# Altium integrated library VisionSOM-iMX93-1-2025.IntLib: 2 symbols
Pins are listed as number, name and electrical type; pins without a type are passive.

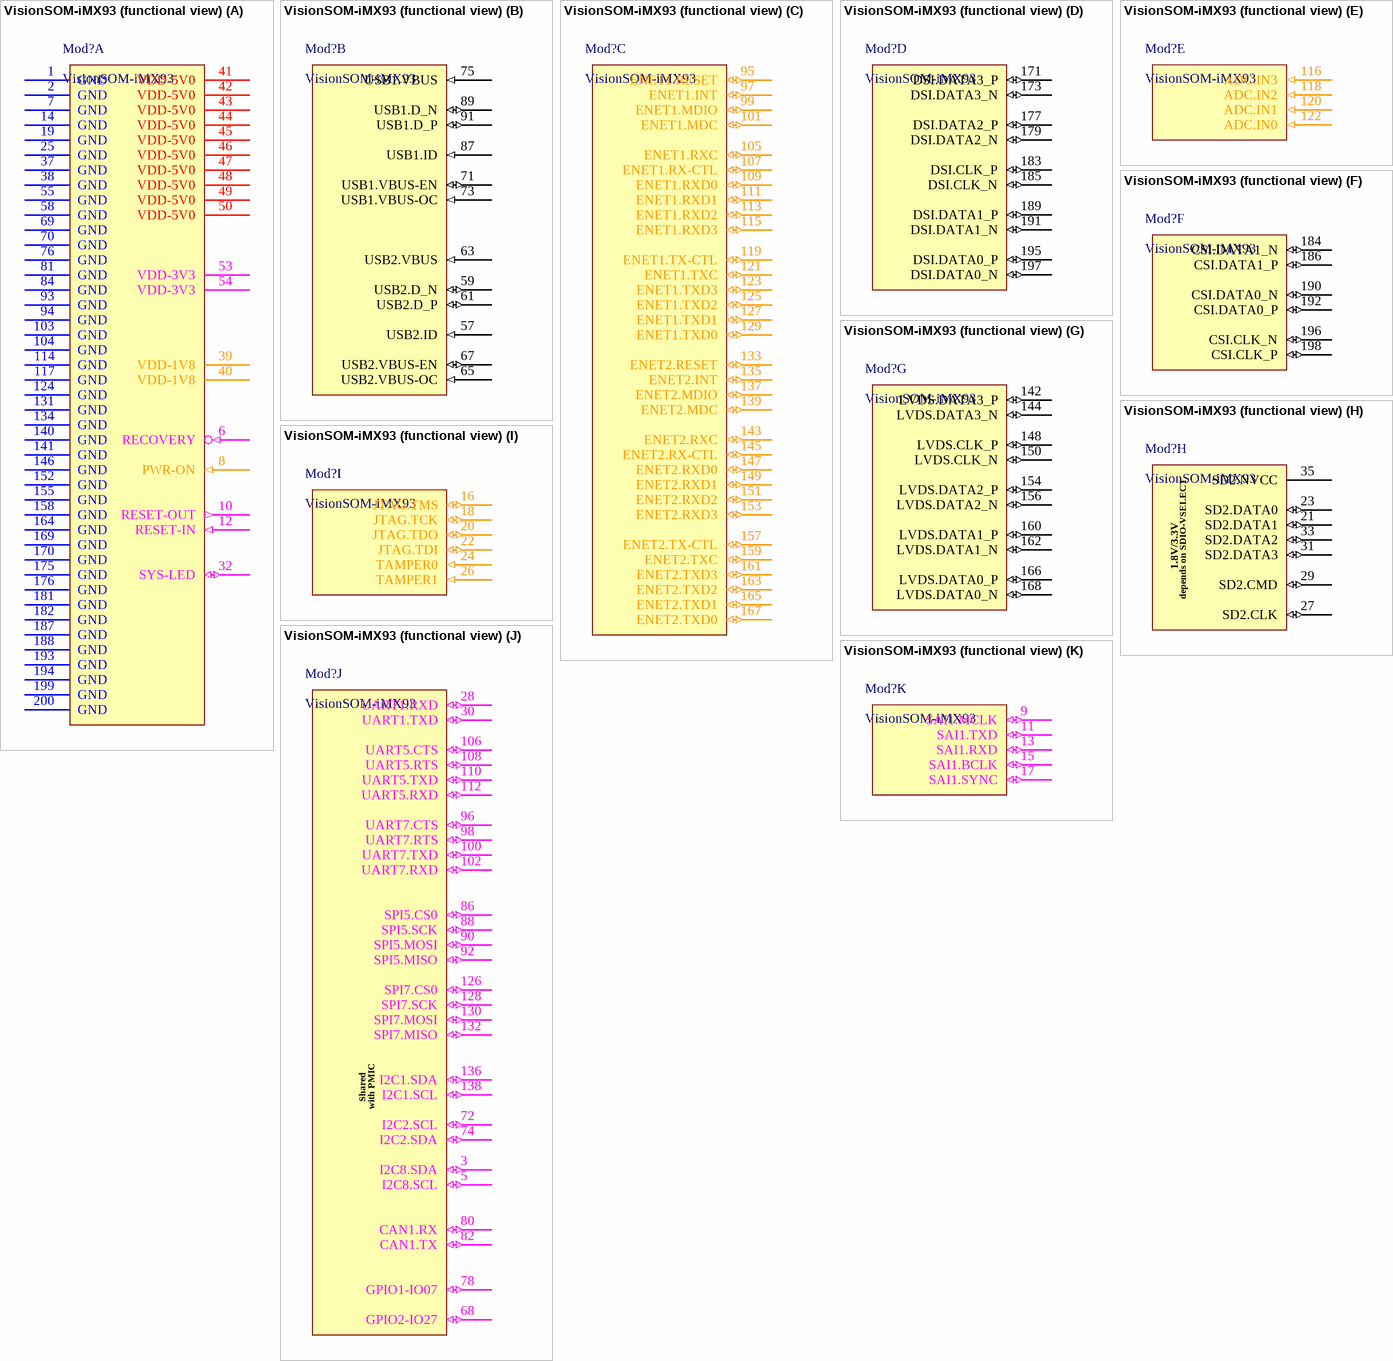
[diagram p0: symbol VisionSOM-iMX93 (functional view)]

## VisionSOM-iMX93 (functional view)
designator Mod?, comment VisionSOM-iMX93
VisionSOM-iMX93 (SLS26 module series)
footprint SODIMM200_1473005-4 (Classic SODIMM200 footprint with SOM mounting hole. / TE 1473005-4)
part A pins: 1 GND (power), 2 GND (power), 6 RECOVERY (in), 7 GND (power), 8 PWR-ON (in), 10 RESET-OUT (out), 12 RESET-IN (in), 14 GND (power), 19 GND (power), 25 GND (power), 32 SYS-LED (io), 37 GND (power), 38 GND (power), 39 VDD-1V8 (power), 40 VDD-1V8 (power), 41 VDD-5V0 (power), 42 VDD-5V0 (power), 43 VDD-5V0 (power), 44 VDD-5V0 (power), 45 VDD-5V0 (power), 46 VDD-5V0 (power), 47 VDD-5V0 (power), 48 VDD-5V0 (power), 49 VDD-5V0 (power), 50 VDD-5V0 (power), 53 VDD-3V3 (power), 54 VDD-3V3 (power), 55 GND (power), 58 GND (power), 69 GND (power), 70 GND (power), 76 GND (power), 81 GND (power), 84 GND (power), 93 GND (power), 94 GND (power), 103 GND (power), 104 GND (power), 114 GND (power), 117 GND (power), 124 GND (power), 131 GND (power), 134 GND (power), 140 GND (power), 141 GND (power), 146 GND (power), 152 GND (power), 155 GND (power), 158 GND (power), 164 GND (power), 169 GND (power), 170 GND (power), 175 GND (power), 176 GND (power), 181 GND (power), 182 GND (power), 187 GND (power), 188 GND (power), 193 GND (power), 194 GND (power), 199 GND (power), 200 GND (power)
part B pins: 57 USB2.ID (in), 59 USB2.D_N (io), 61 USB2.D_P (io), 63 USB2.VBUS (in), 65 USB2.VBUS-OC (in), 67 USB2.VBUS-EN (io), 71 USB1.VBUS-EN (io), 73 USB1.VBUS-OC (in), 75 USB1.VBUS (in), 87 USB1.ID (in), 89 USB1.D_N (io), 91 USB1.D_P (io)
part C pins: 95 ENET1.RESET (io), 97 ENET1.INT (io), 99 ENET1.MDIO (io), 101 ENET1.MDC (io), 105 ENET1.RXC (io), 107 ENET1.RX-CTL (io), 109 ENET1.RXD0 (io), 111 ENET1.RXD1 (io), 113 ENET1.RXD2 (io), 115 ENET1.RXD3 (io), 119 ENET1.TX-CTL (io), 121 ENET1.TXC (io), 123 ENET1.TXD3 (io), 125 ENET1.TXD2 (io), 127 ENET1.TXD1 (io), 129 ENET1.TXD0 (io), 133 ENET2.RESET (io), 135 ENET2.INT (io), 137 ENET2.MDIO (io), 139 ENET2.MDC (io), 143 ENET2.RXC (io), 145 ENET2.RX-CTL (io), 147 ENET2.RXD0 (io), 149 ENET2.RXD1 (io), 151 ENET2.RXD2 (io), 153 ENET2.RXD3 (io), 157 ENET2.TX-CTL (io), 159 ENET2.TXC (io), 161 ENET2.TXD3 (io), 163 ENET2.TXD2 (io), 165 ENET2.TXD1 (io), 167 ENET2.TXD0 (io)
part D pins: 171 DSI.DATA3_P (io), 173 DSI.DATA3_N (io), 177 DSI.DATA2_P (io), 179 DSI.DATA2_N (io), 183 DSI.CLK_P (io), 185 DSI.CLK_N (io), 189 DSI.DATA1_P (io), 191 DSI.DATA1_N (io), 195 DSI.DATA0_P (io), 197 DSI.DATA0_N (io)
part E pins: 116 ADC.IN3 (in), 118 ADC.IN2 (in), 120 ADC.IN1 (in), 122 ADC.IN0 (in)
part F pins: 184 CSI.DATA1_N (io), 186 CSI.DATA1_P (io), 190 CSI.DATA0_N (io), 192 CSI.DATA0_P (io), 196 CSI.CLK_N (io), 198 CSI.CLK_P (io)
part G pins: 142 LVDS.DATA3_P (io), 144 LVDS.DATA3_N (io), 148 LVDS.CLK_P (io), 150 LVDS.CLK_N (io), 154 LVDS.DATA2_P (io), 156 LVDS.DATA2_N (io), 160 LVDS.DATA1_P (io), 162 LVDS.DATA1_N (io), 166 LVDS.DATA0_P (io), 168 LVDS.DATA0_N (io)
part H pins: 21 SD2.DATA1 (io), 23 SD2.DATA0 (io), 27 SD2.CLK (io), 29 SD2.CMD (io), 31 SD2.DATA3 (io), 33 SD2.DATA2 (io), 35 SD2.NVCC (power)
part I pins: 16 JTAG.TMS (io), 18 JTAG.TCK (io), 20 JTAG.TDO (io), 22 JTAG.TDI (io), 24 TAMPER0 (in), 26 TAMPER1 (in)
part J pins: 3 I2C8.SDA (io), 5 I2C8.SCL (io), 28 UART1.RXD (io), 30 UART1.TXD (io), 68 GPIO2-IO27 (io), 72 I2C2.SCL (io), 74 I2C2.SDA (io), 78 GPIO1-IO07 (io), 80 CAN1.RX (io), 82 CAN1.TX (io), 86 SPI5.CS0 (io), 88 SPI5.SCK (io), 90 SPI5.MOSI (io), 92 SPI5.MISO (io), 96 UART7.CTS (io), 98 UART7.RTS (io), 100 UART7.TXD (io), 102 UART7.RXD (io), 106 UART5.CTS (io), 108 UART5.RTS (io), 110 UART5.TXD (io), 112 UART5.RXD (io), 126 SPI7.CS0 (io), 128 SPI7.SCK (io), 130 SPI7.MOSI (io), 132 SPI7.MISO (io), 136 I2C1.SDA (io), 138 I2C1.SCL (io)
part K pins: 9 SAI1.MCLK (io), 11 SAI1.TXD (io), 13 SAI1.RXD (io), 15 SAI1.BCLK (io), 17 SAI1.SYNC (io)

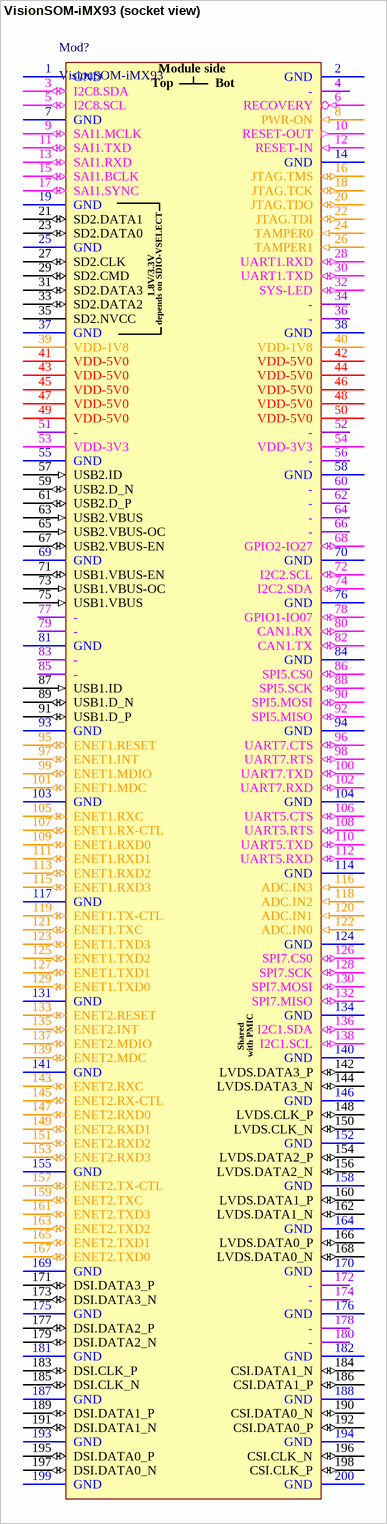
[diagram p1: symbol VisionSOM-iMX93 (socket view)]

## VisionSOM-iMX93 (socket view)
designator Mod?, comment VisionSOM-iMX93
VisionSOM-iMX93 (SLS26 module series)
footprint SODIMM200_1473005-4 (Classic SODIMM200 footprint with SOM mounting hole. / TE 1473005-4)
pins: 1 GND (power), 2 GND (power), 3 I2C8.SDA (io), 4 -, 5 I2C8.SCL (io), 6 RECOVERY (in), 7 GND (power), 8 PWR-ON (in), 9 SAI1.MCLK (io), 10 RESET-OUT (out), 11 SAI1.TXD (io), 12 RESET-IN (in), 13 SAI1.RXD (io), 14 GND (power), 15 SAI1.BCLK (io), 16 JTAG.TMS (io), 17 SAI1.SYNC (io), 18 JTAG.TCK (io), 19 GND (power), 20 JTAG.TDO (io), 21 SD2.DATA1 (io), 22 JTAG.TDI (io), 23 SD2.DATA0 (io), 24 TAMPER0 (in), 25 GND (power), 26 TAMPER1 (in), 27 SD2.CLK (io), 28 UART1.RXD (io), 29 SD2.CMD (io), 30 UART1.TXD (io), 31 SD2.DATA3 (io), 32 SYS-LED (io), 33 SD2.DATA2 (io), 34 -, 35 SD2.NVCC (power), 36 -, 37 GND (power), 38 GND (power), 39 VDD-1V8 (power), 40 VDD-1V8 (power), 41 VDD-5V0 (power), 42 VDD-5V0 (power), 43 VDD-5V0 (power), 44 VDD-5V0 (power), 45 VDD-5V0 (power), 46 VDD-5V0 (power), 47 VDD-5V0 (power), 48 VDD-5V0 (power), 49 VDD-5V0 (power), 50 VDD-5V0 (power), 51 -, 52 -, 53 VDD-3V3 (power), 54 VDD-3V3 (power), 55 GND (power), 56 -, 57 USB2.ID (in), 58 GND (power), 59 USB2.D_N (io), 60 -, 61 USB2.D_P (io), 62 -, 63 USB2.VBUS (in), 64 -, 65 USB2.VBUS-OC (in), 66 -, 67 USB2.VBUS-EN (io), 68 GPIO2-IO27 (io), 69 GND (power), 70 GND (power), 71 USB1.VBUS-EN (io), 72 I2C2.SCL (io), 73 USB1.VBUS-OC (in), 74 I2C2.SDA (io), 75 USB1.VBUS (in), 76 GND (power), 77 -, 78 GPIO1-IO07 (io), 79 -, 80 CAN1.RX (io), 81 GND (power), 82 CAN1.TX (io), 83 -, 84 GND (power), 85 -, 86 SPI5.CS0 (io), 87 USB1.ID (in), 88 SPI5.SCK (io), 89 USB1.D_N (io), 90 SPI5.MOSI (io), 91 USB1.D_P (io), 92 SPI5.MISO (io), 93 GND (power), 94 GND (power), 95 ENET1.RESET (io), 96 UART7.CTS (io), 97 ENET1.INT (io), 98 UART7.RTS (io), 99 ENET1.MDIO (io), 100 UART7.TXD (io), 101 ENET1.MDC (io), 102 UART7.RXD (io), 103 GND (power), 104 GND (power), 105 ENET1.RXC (io), 106 UART5.CTS (io), 107 ENET1.RX-CTL (io), 108 UART5.RTS (io), 109 ENET1.RXD0 (io), 110 UART5.TXD (io), 111 ENET1.RXD1 (io), 112 UART5.RXD (io), 113 ENET1.RXD2 (io), 114 GND (power), 115 ENET1.RXD3 (io), 116 ADC.IN3 (in), 117 GND (power), 118 ADC.IN2 (in), 119 ENET1.TX-CTL (io), 120 ADC.IN1 (in), 121 ENET1.TXC (io), 122 ADC.IN0 (in), 123 ENET1.TXD3 (io), 124 GND (power), 125 ENET1.TXD2 (io), 126 SPI7.CS0 (io), 127 ENET1.TXD1 (io), 128 SPI7.SCK (io), 129 ENET1.TXD0 (io), 130 SPI7.MOSI (io), 131 GND (power), 132 SPI7.MISO (io), 133 ENET2.RESET (io), 134 GND (power), 135 ENET2.INT (io), 136 I2C1.SDA (io), 137 ENET2.MDIO (io), 138 I2C1.SCL (io), 139 ENET2.MDC (io), 140 GND (power), 141 GND (power), 142 LVDS.DATA3_P (io), 143 ENET2.RXC (io), 144 LVDS.DATA3_N (io), 145 ENET2.RX-CTL (io), 146 GND (power), 147 ENET2.RXD0 (io), 148 LVDS.CLK_P (io), 149 ENET2.RXD1 (io), 150 LVDS.CLK_N (io), 151 ENET2.RXD2 (io), 152 GND (power), 153 ENET2.RXD3 (io), 154 LVDS.DATA2_P (io), 155 GND (power), 156 LVDS.DATA2_N (io), 157 ENET2.TX-CTL (io), 158 GND (power), 159 ENET2.TXC (io), 160 LVDS.DATA1_P (io), 161 ENET2.TXD3 (io), 162 LVDS.DATA1_N (io), 163 ENET2.TXD2 (io), 164 GND (power), 165 ENET2.TXD1 (io), 166 LVDS.DATA0_P (io), 167 ENET2.TXD0 (io), 168 LVDS.DATA0_N (io), 169 GND (power), 170 GND (power), 171 DSI.DATA3_P (io), 172 -, 173 DSI.DATA3_N (io), 174 -, 175 GND (power), 176 GND (power), 177 DSI.DATA2_P (io), 178 -, 179 DSI.DATA2_N (io), 180 -, 181 GND (power), 182 GND (power), 183 DSI.CLK_P (io), 184 CSI.DATA1_N (io), 185 DSI.CLK_N (io), 186 CSI.DATA1_P (io), 187 GND (power), 188 GND (power), 189 DSI.DATA1_P (io), 190 CSI.DATA0_N (io), 191 DSI.DATA1_N (io), 192 CSI.DATA0_P (io), 193 GND (power), 194 GND (power), 195 DSI.DATA0_P (io), 196 CSI.CLK_N (io), 197 DSI.DATA0_N (io), 198 CSI.CLK_P (io), 199 GND (power), 200 GND (power)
